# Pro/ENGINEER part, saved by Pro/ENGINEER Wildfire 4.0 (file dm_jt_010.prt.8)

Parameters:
  METRIC = "NO"

Other parameters: PITCH, DRILL_POINT_ANGLE, DRILL_DEPTH, DRILL_DIAMETER, THREAD_DIAMETER, THREADS_PER_INCH, THREAD_DEPTH, THREAD_LENGTH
